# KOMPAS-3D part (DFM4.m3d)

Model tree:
1. Эскиз:1
2. Операция выдавливания:1
     Расстояние 1 = 4.5375
3. Эскиз:2
4. Операция выдавливания:2
     Расстояние 1 = 8.2
5. Смещенная плоскость:1
     Расстояние = 57.75
6. Эскиз:3
7. Эскиз:4
8. Эскиз:5
9. Операция по сечениям:1
10. Эскиз:7
11. Эскиз:8
12. Кинематическая операция:2
13. Массив по концентрической сетке:2  (with: Кинематическая операция:2)  (6 pattern instances)
     Геометрический массив = 5; Шаг 2 = 360; Номер 2 = 1
14. Эскиз:9
15. Вырезать элемент выдавливания:1
     Расстояние 1 = 50
16. Эскиз:10
17. Смещенная плоскость:2
     Расстояние = 16
18. Эскиз:11
19. Вырезать элемент по сечениям:1
20. Вырезать элемент выдавливания:2
     Расстояние 1 = 9
21. Эскиз:12
22. Смещенная плоскость:3
     Расстояние = 5
23. Эскиз:14
24. Вырезать элемент по сечениям:2
25. Эскиз:15
26. Вырезать элемент выдавливания:3
     Расстояние 1 = 9
27. Фаска:1
     Угол = 40; Длина 1 = 0.8; Длина 2 = 0.67128
28. Фаска:2
     Угол = 40; Длина 1 = 0.8; Длина 2 = 0.67128
29. Фаска:3
     Угол = 45; Длина 1 = 2; Длина 2 = 2
